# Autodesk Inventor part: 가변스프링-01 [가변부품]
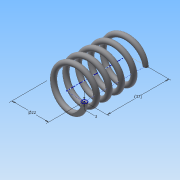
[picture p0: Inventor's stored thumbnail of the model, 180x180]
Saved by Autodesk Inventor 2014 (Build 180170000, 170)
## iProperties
Created: 2015-09
Part Number: 가변스프링-01 [가변부품]
Material: 강철, 탄소
Document SubType Name: Modeling
Designer: study
Density: 7.87 g/cm^3
Appearance: 반연마
Mass: 18.9156 g
Surface Area: 32.5757 cm^2
Volume: 2.40351 cm^3
Author: study
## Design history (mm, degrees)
sketch "스케치1"
  geometry: L1 (0, 0)-(11, 0); L2 (11, 0)-(11, 39.945); L3 (11, 39.945)-(0, 39.945); L4 (0, 39.945)-(0, 0); C1 r 1.5 at (11, 0)
  constraints: 8 end point, 2 parallel, 1 centre point, 1 coincident, 1 horizontal, 1 perpendicular
  dimensions: "d0" = 22 diameter of L2 L4; "d1" = 39.9455 distance of L1.end L2.end (derived); "d2" = 3 diameter of C1
feature "코일1" pitch "d3" = 10; turns "d5" = 5; dims "d4" = 39.9455 (= d1), "d6" = 0, angle "d7" = 90 deg, angle "d8" = 90 deg, "d9" = 0, "d10" = 0
node "작업 평면1"
sketch "스케치2"
  geometry: L1 (-12.5, 0)-(-9.5, 0) reference; 1 further point
  constraints: 1 horizontal alignment
extrude "돌출1" cut sketch "스케치2" stored distance "d12" = 10; taper "d13" = 0 deg
node "작업 평면2"
sketch "스케치3"
  geometry: L1 (-9.5, 0)-(-12.5, 0) reference; 1 further point
  constraints: 1 horizontal alignment
extrude "돌출2" cut sketch "스케치3" stored distance "d15" = 10; taper "d16" = 0 deg
node "솔리드1"
node "절단 모서리 투영1"
node "절단 모서리 투영2"
other parameters: "d11" = 0, "d14" = 39.9455 (= d1)
